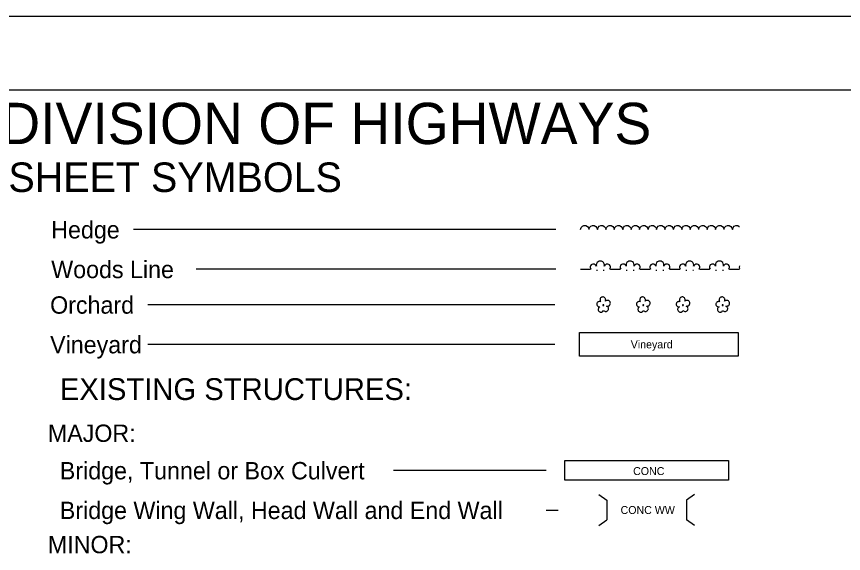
# Model space of a CAD drawing. Extents: x 0 to 3, y 0 to 1.83.
# Drawn here: x 1.443 to 2.143, y 1.378 to 1.833 of the extents above; entities that cross this region are included whole.
import ezdxf

# ---------------------------------------------------------------- set-up
doc = ezdxf.new("R2010")
doc.units = 0
for name, color, linetype in [('Sheet_Plan', 7, 'Continuous'), ('Sheet_Symbology', 7, 'Continuous'), ('z - Construction', 7, 'Continuous')]:
    doc.layers.add(name, color=color, linetype=linetype)

msp = doc.modelspace()

# ---------------------------------------------------------------- linework, layer by layer
at = {"layer": 'Sheet_Plan'}
msp.add_line((2.77083, 1.77083), (0.06249, 1.77083), dxfattribs=at)
at = {"layer": 'Sheet_Symbology'}
for p, q in [((1.89995, 1.6528), (1.54231, 1.6528)), ((1.92079, 1.6528), (1.9213, 1.6544)), ((1.9213, 1.6544), (1.92231, 1.65549)), ((1.92231, 1.65549), (1.92365, 1.65625)), ((1.92365, 1.65625), (1.92525, 1.65625)), ((1.92525, 1.65625), (1.92659, 1.65541)), ((1.92659, 1.65541), (1.92752, 1.65431)), ((1.92752, 1.65431), (1.92786, 1.65288)), ((1.92794, 1.6528), (1.92844, 1.6544)), ((1.92844, 1.6544), (1.92945, 1.65549)), ((1.92945, 1.65549), (1.9308, 1.65625)), ((1.9308, 1.65625), (1.9324, 1.65625)), ((1.9324, 1.65625), (1.93374, 1.65541)), ((1.93374, 1.65541), (1.93467, 1.65431)), ((1.93467, 1.65431), (1.935, 1.65288)), ((1.93509, 1.6528), (1.93559, 1.6544)), ((1.93559, 1.6544), (1.9366, 1.65549)), ((1.9366, 1.65549), (1.93795, 1.65625)), ((1.93795, 1.65625), (1.93954, 1.65625)), ((1.93954, 1.65625), (1.94089, 1.65541)), ((1.94089, 1.65541), (1.94181, 1.65431)), ((1.94181, 1.65431), (1.94215, 1.65288)), ((1.94223, 1.6528), (1.94274, 1.6544)), ((1.94274, 1.6544), (1.94375, 1.65549)), ((1.94375, 1.65549), (1.94509, 1.65625)), ((1.94509, 1.65625), (1.94669, 1.65625)), ((1.94669, 1.65625), (1.94803, 1.65541)), ((1.94803, 1.65541), (1.94896, 1.65431)), ((1.94896, 1.65431), (1.9493, 1.65288)), ((1.94938, 1.6528), (1.94988, 1.6544)), ((1.94988, 1.6544), (1.95089, 1.65549)), ((1.95089, 1.65549), (1.95224, 1.65625)), ((1.95224, 1.65625), (1.95384, 1.65625)), ((1.95384, 1.65625), (1.95518, 1.65541)), ((1.95518, 1.65541), (1.95611, 1.65431)), ((1.95611, 1.65431), (1.95644, 1.65288)), ((1.95653, 1.6528), (1.95703, 1.6544)), ((1.95703, 1.6544), (1.95804, 1.65549)), ((1.95804, 1.65549), (1.95939, 1.65625)), ((1.95939, 1.65625), (1.96098, 1.65625)), ((1.96098, 1.65625), (1.96233, 1.65541)), ((1.96233, 1.65541), (1.96325, 1.65431)), ((1.96325, 1.65431), (1.96359, 1.65288)), ((1.96367, 1.6528), (1.96418, 1.6544)), ((1.96418, 1.6544), (1.96519, 1.65549)), ((1.96519, 1.65549), (1.96653, 1.65625)), ((1.96653, 1.65625), (1.96813, 1.65625)), ((1.96813, 1.65625), (1.96947, 1.65541)), ((1.96947, 1.65541), (1.9704, 1.65431)), ((1.9704, 1.65431), (1.97074, 1.65288)), ((1.97082, 1.6528), (1.97132, 1.6544)), ((1.97132, 1.6544), (1.97233, 1.65549)), ((1.97233, 1.65549), (1.97368, 1.65625)), ((1.97368, 1.65625), (1.97528, 1.65625)), ((1.97528, 1.65625), (1.97662, 1.65541)), ((1.97662, 1.65541), (1.97755, 1.65431)), ((1.97755, 1.65431), (1.97788, 1.65288)), ((1.97797, 1.6528), (1.97847, 1.6544)), ((1.97847, 1.6544), (1.97948, 1.65549)), ((1.97948, 1.65549), (1.98083, 1.65625)), ((1.98083, 1.65625), (1.98242, 1.65625)), ((1.98242, 1.65625), (1.98377, 1.65541)), ((1.98377, 1.65541), (1.98469, 1.65431)), ((1.98469, 1.65431), (1.98503, 1.65288)), ((1.98511, 1.6528), (1.98562, 1.6544)), ((1.98562, 1.6544), (1.98663, 1.65549)), ((1.98663, 1.65549), (1.98797, 1.65625)), ((1.98797, 1.65625), (1.98957, 1.65625)), ((1.98957, 1.65625), (1.99091, 1.65541)), ((1.99091, 1.65541), (1.99184, 1.65431)), ((1.99184, 1.65431), (1.99218, 1.65288)), ((1.99226, 1.6528), (1.99276, 1.6544)), ((1.99276, 1.6544), (1.99377, 1.65549)), ((1.99377, 1.65549), (1.99512, 1.65625)), ((1.99512, 1.65625), (1.99672, 1.65625)), ((1.99672, 1.65625), (1.99806, 1.65541)), ((1.99806, 1.65541), (1.99899, 1.65431)), ((1.99899, 1.65431), (1.99932, 1.65288)), ((1.99941, 1.6528), (1.99991, 1.6544)), ((1.99991, 1.6544), (2.00092, 1.65549)), ((2.00092, 1.65549), (2.00227, 1.65625)), ((2.00227, 1.65625), (2.00386, 1.65625)), ((2.00386, 1.65625), (2.00521, 1.65541)), ((2.00521, 1.65541), (2.00613, 1.65431)), ((2.00613, 1.65431), (2.00647, 1.65288)), ((2.00655, 1.6528), (2.00706, 1.6544)), ((2.00706, 1.6544), (2.00807, 1.65549)), ((2.00807, 1.65549), (2.00941, 1.65625)), ((2.00941, 1.65625), (2.01101, 1.65625)), ((2.01101, 1.65625), (2.01235, 1.65541)), ((2.01235, 1.65541), (2.01328, 1.65431)), ((2.01328, 1.65431), (2.01362, 1.65288)), ((2.0137, 1.6528), (2.0142, 1.6544)), ((2.0142, 1.6544), (2.01521, 1.65549)), ((2.01521, 1.65549), (2.01656, 1.65625)), ((2.01656, 1.65625), (2.01816, 1.65625)), ((2.01816, 1.65625), (2.0195, 1.65541)), ((2.0195, 1.65541), (2.02043, 1.65431)), ((2.02043, 1.65431), (2.02076, 1.65288)), ((2.02085, 1.6528), (2.02135, 1.6544)), ((2.02135, 1.6544), (2.02236, 1.65549)), ((2.02236, 1.65549), (2.02371, 1.65625)), ((2.02371, 1.65625), (2.0253, 1.65625)), ((2.0253, 1.65625), (2.02665, 1.65541)), ((2.02665, 1.65541), (2.02757, 1.65431)), ((2.02757, 1.65431), (2.02791, 1.65288)), ((2.02799, 1.6528), (2.0285, 1.6544)), ((2.0285, 1.6544), (2.02951, 1.65549)), ((2.02951, 1.65549), (2.03085, 1.65625)), ((2.03085, 1.65625), (2.03245, 1.65625)), ((2.03245, 1.65625), (2.03379, 1.65541)), ((2.03379, 1.65541), (2.03472, 1.65431)), ((2.03472, 1.65431), (2.03506, 1.65288)), ((2.03514, 1.6528), (2.03564, 1.6544)), ((2.03564, 1.6544), (2.03665, 1.65549)), ((2.03665, 1.65549), (2.038, 1.65625)), ((2.038, 1.65625), (2.0396, 1.65625)), ((2.0396, 1.65625), (2.04094, 1.65541)), ((2.04094, 1.65541), (2.04187, 1.65431)), ((2.04187, 1.65431), (2.0422, 1.65288)), ((2.04229, 1.6528), (2.04279, 1.6544)), ((2.04279, 1.6544), (2.0438, 1.65549)), ((2.0438, 1.65549), (2.04515, 1.65625)), ((2.04515, 1.65625), (2.04674, 1.65625)), ((2.04674, 1.65625), (2.04809, 1.65541)), ((2.04809, 1.65541), (2.04901, 1.65431)), ((2.04901, 1.65431), (2.04935, 1.65288)), ((2.04943, 1.6528), (2.04994, 1.6544)), ((2.04994, 1.6544), (2.05095, 1.65549)), ((2.05095, 1.65549), (2.05229, 1.65625)), ((2.05229, 1.65625), (2.05389, 1.65625)), ((2.05389, 1.65625), (2.05523, 1.65541)), ((2.05523, 1.65541), (2.05532, 1.65532)), ((1.89995, 1.61917), (1.59538, 1.61917)), ((1.92079, 1.61917), (1.9292, 1.61917)), ((1.93416, 1.61833), (1.935, 1.61833)), ((1.94005, 1.61833), (1.94089, 1.61833)), ((1.94602, 1.61917), (1.95442, 1.61917)), ((1.95939, 1.61833), (1.96023, 1.61833)), ((1.96527, 1.61833), (1.96611, 1.61833)), ((1.97124, 1.61917), (1.97965, 1.61917)), ((1.98461, 1.61833), (1.98545, 1.61833)), ((1.99049, 1.61833), (1.99134, 1.61833)), ((1.99646, 1.61917), (2.00487, 1.61917)), ((2.00983, 1.61833), (2.01067, 1.61833)), ((2.01572, 1.61833), (2.01656, 1.61833)), ((2.02169, 1.61917), (2.0301, 1.61917)), ((2.03506, 1.61833), (2.0359, 1.61833)), ((2.04094, 1.61833), (2.04178, 1.61833)), ((2.04691, 1.61917), (2.05532, 1.61917)), ((1.899, 1.58902), (1.55439, 1.58902)), ((1.899, 1.55539), (1.55439, 1.55539)), ((1.89175, 1.4486), (1.76232, 1.4486)), ((1.93622, 1.42819), (1.94312, 1.42338)), ((1.94312, 1.42338), (1.94312, 1.40656)), ((2.01728, 1.42819), (2.01038, 1.42338)), ((2.01038, 1.42338), (2.01038, 1.40656)), ((1.89175, 1.41497), (1.90182, 1.41497)), ((1.93622, 1.40175), (1.94312, 1.40656)), ((2.01728, 1.40175), (2.01038, 1.40656))]:
    msp.add_line(p, q, dxfattribs=at)
for points in [[(1.94179, 1.59196), (1.94204, 1.59247), (1.94212, 1.59297), (1.94204, 1.59348), (1.94196, 1.59398), (1.9417, 1.5944), (1.94145, 1.59482), (1.94103, 1.59516), (1.94061, 1.59541), (1.94002, 1.59558), (1.9396, 1.59558), (1.9391, 1.5955), (1.93859, 1.59533), (1.93817, 1.59508), (1.93775, 1.59474), (1.9375, 1.59423), (1.93733, 1.59381), (1.93725, 1.59331), (1.93725, 1.59281), (1.93733, 1.5923), (1.93758, 1.59188), (1.93792, 1.59138), (1.9375, 1.59163), (1.93699, 1.59171), (1.93649, 1.59171), (1.93607, 1.59154), (1.93565, 1.59138), (1.93523, 1.59104), (1.93489, 1.5907), (1.93464, 1.59028), (1.93456, 1.58986), (1.93447, 1.58927), (1.93456, 1.58885), (1.93472, 1.58843), (1.93506, 1.58801), (1.93531, 1.58768), (1.93573, 1.58742), (1.93624, 1.58717), (1.93666, 1.58709), (1.93716, 1.58709), (1.93674, 1.58692), (1.93632, 1.58658), (1.93607, 1.58625), (1.9359, 1.58574), (1.93573, 1.58524), (1.93573, 1.58482), (1.93582, 1.58431), (1.93607, 1.58389), (1.93632, 1.58347), (1.93666, 1.58314), (1.93708, 1.58288), (1.9375, 1.58272), (1.938, 1.58272), (1.93851, 1.58272), (1.93893, 1.5828), (1.93935, 1.58314), (1.93977, 1.58339), (1.94019, 1.58415)], [(1.94019, 1.58415), (1.9412, 1.58356), (1.9417, 1.58339), (1.94221, 1.5833), (1.94271, 1.58339), (1.94313, 1.58356), (1.94355, 1.58381), (1.94397, 1.58415), (1.94423, 1.58457), (1.94439, 1.58499), (1.94456, 1.58549), (1.94448, 1.586), (1.94439, 1.5865), (1.94406, 1.587), (1.94381, 1.58734), (1.94338, 1.58759), (1.94288, 1.58785), (1.94338, 1.58776), (1.94397, 1.58776), (1.94439, 1.58793), (1.9449, 1.58818), (1.94532, 1.58843), (1.94565, 1.58885), (1.94591, 1.58936), (1.94599, 1.58986), (1.94608, 1.59037), (1.94599, 1.59087), (1.94582, 1.59138), (1.94549, 1.5918), (1.94507, 1.59222), (1.94465, 1.59247), (1.94414, 1.59264), (1.94364, 1.59272), (1.94313, 1.59272), (1.94263, 1.59255), (1.94221, 1.5923), (1.94179, 1.59196)], [(1.97542, 1.59196), (1.97567, 1.59247), (1.97575, 1.59297), (1.97567, 1.59348), (1.97559, 1.59398), (1.97533, 1.5944), (1.97508, 1.59482), (1.97466, 1.59516), (1.97424, 1.59541), (1.97365, 1.59558), (1.97323, 1.59558), (1.97273, 1.5955), (1.97222, 1.59533), (1.9718, 1.59508), (1.97138, 1.59474), (1.97113, 1.59423), (1.97096, 1.59381), (1.97088, 1.59331), (1.97088, 1.59281), (1.97096, 1.5923), (1.97121, 1.59188), (1.97155, 1.59138), (1.97113, 1.59163), (1.97063, 1.59171), (1.97012, 1.59171), (1.9697, 1.59154), (1.96928, 1.59138), (1.96886, 1.59104), (1.96852, 1.5907), (1.96827, 1.59028), (1.96819, 1.58986), (1.9681, 1.58927), (1.96819, 1.58885), (1.96836, 1.58843), (1.96869, 1.58801), (1.96894, 1.58768), (1.96937, 1.58742), (1.96987, 1.58717), (1.97029, 1.58709), (1.97079, 1.58709), (1.97037, 1.58692), (1.96995, 1.58658), (1.9697, 1.58625), (1.96953, 1.58574), (1.96937, 1.58524), (1.96937, 1.58482), (1.96945, 1.58431), (1.9697, 1.58389), (1.96995, 1.58347), (1.97029, 1.58314), (1.97071, 1.58288), (1.97113, 1.58272), (1.97164, 1.58272), (1.97214, 1.58272), (1.97256, 1.5828), (1.97298, 1.58314), (1.9734, 1.58339), (1.97382, 1.58415)], [(1.97382, 1.58415), (1.97483, 1.58356), (1.97533, 1.58339), (1.97584, 1.5833), (1.97634, 1.58339), (1.97676, 1.58356), (1.97718, 1.58381), (1.9776, 1.58415), (1.97786, 1.58457), (1.97803, 1.58499), (1.97819, 1.58549), (1.97811, 1.586), (1.97803, 1.5865), (1.97769, 1.587), (1.97744, 1.58734), (1.97702, 1.58759), (1.97651, 1.58785), (1.97702, 1.58776), (1.9776, 1.58776), (1.97803, 1.58793), (1.97853, 1.58818), (1.97895, 1.58843), (1.97929, 1.58885), (1.97954, 1.58936), (1.97962, 1.58986), (1.97971, 1.59037), (1.97962, 1.59087), (1.97945, 1.59138), (1.97912, 1.5918), (1.9787, 1.59222), (1.97828, 1.59247), (1.97777, 1.59264), (1.97727, 1.59272), (1.97676, 1.59272), (1.97626, 1.59255), (1.97584, 1.5923), (1.97542, 1.59196)], [(2.00905, 1.59196), (2.0093, 1.59247), (2.00939, 1.59297), (2.0093, 1.59348), (2.00922, 1.59398), (2.00897, 1.5944), (2.00871, 1.59482), (2.00829, 1.59516), (2.00787, 1.59541), (2.00728, 1.59558), (2.00686, 1.59558), (2.00636, 1.5955), (2.00585, 1.59533), (2.00543, 1.59508), (2.00501, 1.59474), (2.00476, 1.59423), (2.00459, 1.59381), (2.00451, 1.59331), (2.00451, 1.59281), (2.00459, 1.5923), (2.00485, 1.59188), (2.00518, 1.59138), (2.00476, 1.59163), (2.00426, 1.59171), (2.00375, 1.59171), (2.00333, 1.59154), (2.00291, 1.59138), (2.00249, 1.59104), (2.00216, 1.5907), (2.0019, 1.59028), (2.00182, 1.58986), (2.00174, 1.58927), (2.00182, 1.58885), (2.00199, 1.58843), (2.00232, 1.58801), (2.00258, 1.58768), (2.003, 1.58742), (2.0035, 1.58717), (2.00392, 1.58709), (2.00443, 1.58709), (2.00401, 1.58692), (2.00358, 1.58658), (2.00333, 1.58625), (2.00316, 1.58574), (2.003, 1.58524), (2.003, 1.58482), (2.00308, 1.58431), (2.00333, 1.58389), (2.00358, 1.58347), (2.00392, 1.58314), (2.00434, 1.58288), (2.00476, 1.58272), (2.00527, 1.58272), (2.00577, 1.58272), (2.00619, 1.5828), (2.00661, 1.58314), (2.00703, 1.58339), (2.00745, 1.58415)], [(2.00745, 1.58415), (2.00846, 1.58356), (2.00897, 1.58339), (2.00947, 1.5833), (2.00997, 1.58339), (2.0104, 1.58356), (2.01082, 1.58381), (2.01124, 1.58415), (2.01149, 1.58457), (2.01166, 1.58499), (2.01182, 1.58549), (2.01174, 1.586), (2.01166, 1.5865), (2.01132, 1.587), (2.01107, 1.58734), (2.01065, 1.58759), (2.01014, 1.58785), (2.01065, 1.58776), (2.01124, 1.58776), (2.01166, 1.58793), (2.01216, 1.58818), (2.01258, 1.58843), (2.01292, 1.58885), (2.01317, 1.58936), (2.01325, 1.58986), (2.01334, 1.59037), (2.01325, 1.59087), (2.01309, 1.59138), (2.01275, 1.5918), (2.01233, 1.59222), (2.01191, 1.59247), (2.0114, 1.59264), (2.0109, 1.59272), (2.0104, 1.59272), (2.00989, 1.59255), (2.00947, 1.5923), (2.00905, 1.59196)], [(2.04268, 1.59196), (2.04293, 1.59247), (2.04302, 1.59297), (2.04293, 1.59348), (2.04285, 1.59398), (2.0426, 1.5944), (2.04234, 1.59482), (2.04192, 1.59516), (2.0415, 1.59541), (2.04092, 1.59558), (2.0405, 1.59558), (2.03999, 1.5955), (2.03949, 1.59533), (2.03907, 1.59508), (2.03865, 1.59474), (2.03839, 1.59423), (2.03823, 1.59381), (2.03814, 1.59331), (2.03814, 1.59281), (2.03823, 1.5923), (2.03848, 1.59188), (2.03881, 1.59138), (2.03839, 1.59163), (2.03789, 1.59171), (2.03738, 1.59171), (2.03696, 1.59154), (2.03654, 1.59138), (2.03612, 1.59104), (2.03579, 1.5907), (2.03553, 1.59028), (2.03545, 1.58986), (2.03537, 1.58927), (2.03545, 1.58885), (2.03562, 1.58843), (2.03595, 1.58801), (2.03621, 1.58768), (2.03663, 1.58742), (2.03713, 1.58717), (2.03755, 1.58709), (2.03806, 1.58709), (2.03764, 1.58692), (2.03722, 1.58658), (2.03696, 1.58625), (2.0368, 1.58574), (2.03663, 1.58524), (2.03663, 1.58482), (2.03671, 1.58431), (2.03696, 1.58389), (2.03722, 1.58347), (2.03755, 1.58314), (2.03797, 1.58288), (2.03839, 1.58272), (2.0389, 1.58272), (2.0394, 1.58272), (2.03982, 1.5828), (2.04024, 1.58314), (2.04066, 1.58339), (2.04108, 1.58415)], [(2.04108, 1.58415), (2.04209, 1.58356), (2.0426, 1.58339), (2.0431, 1.5833), (2.04361, 1.58339), (2.04403, 1.58356), (2.04445, 1.58381), (2.04487, 1.58415), (2.04512, 1.58457), (2.04529, 1.58499), (2.04546, 1.58549), (2.04537, 1.586), (2.04529, 1.5865), (2.04495, 1.587), (2.0447, 1.58734), (2.04428, 1.58759), (2.04377, 1.58785), (2.04428, 1.58776), (2.04487, 1.58776), (2.04529, 1.58793), (2.04579, 1.58818), (2.04621, 1.58843), (2.04655, 1.58885), (2.0468, 1.58936), (2.04689, 1.58986), (2.04697, 1.59037), (2.04689, 1.59087), (2.04672, 1.59138), (2.04638, 1.5918), (2.04596, 1.59222), (2.04554, 1.59247), (2.04504, 1.59264), (2.04453, 1.59272), (2.04403, 1.59272), (2.04352, 1.59255), (2.0431, 1.5923), (2.04268, 1.59196)], [(1.94036, 1.58902), (1.94011, 1.58902), (1.93994, 1.58894), (1.93977, 1.58885), (1.93977, 1.5886), (1.93977, 1.58843), (1.93994, 1.58827), (1.94019, 1.58827), (1.94036, 1.58827), (1.94053, 1.58843), (1.94061, 1.58869), (1.94053, 1.58885), (1.94036, 1.58902)], [(1.97399, 1.58902), (1.97374, 1.58902), (1.97357, 1.58894), (1.9734, 1.58885), (1.9734, 1.5886), (1.9734, 1.58843), (1.97357, 1.58827), (1.97382, 1.58827), (1.97399, 1.58827), (1.97416, 1.58843), (1.97424, 1.58869), (1.97416, 1.58885), (1.97399, 1.58902)], [(2.00762, 1.58902), (2.00737, 1.58902), (2.0072, 1.58894), (2.00703, 1.58885), (2.00703, 1.5886), (2.00703, 1.58843), (2.0072, 1.58827), (2.00745, 1.58827), (2.00762, 1.58827), (2.00779, 1.58843), (2.00787, 1.58869), (2.00779, 1.58885), (2.00762, 1.58902)], [(2.04125, 1.58902), (2.041, 1.58902), (2.04083, 1.58894), (2.04066, 1.58885), (2.04066, 1.5886), (2.04066, 1.58843), (2.04083, 1.58827), (2.04108, 1.58827), (2.04125, 1.58827), (2.04142, 1.58843), (2.0415, 1.58869), (2.04142, 1.58885), (2.04125, 1.58902)], [(1.91984, 1.56548), (2.05437, 1.56548), (2.05437, 1.5453), (1.91984, 1.5453), (1.91984, 1.56548)], [(1.90739, 1.45701), (2.04611, 1.45701), (2.04611, 1.44019), (1.90739, 1.44019), (1.90739, 1.45701)]]:
    msp.add_lwpolyline(points, dxfattribs=at)
for centre, radius, start, end in [((1.93753, 1.62256), 0.00347, 345.96376, 194.03624), ((1.96274, 1.62256), 0.00347, 345.96376, 194.03624), ((1.98797, 1.62256), 0.00347, 345.96376, 194.03624), ((2.01319, 1.62256), 0.00347, 345.96376, 194.03624), ((2.03841, 1.62256), 0.00347, 345.96376, 194.03624), ((1.93164, 1.62087), 0.00266, 18.43495, 219.23152), ((1.94341, 1.62087), 0.00266, 320.76848, 161.56505), ((1.95686, 1.62087), 0.00266, 18.43495, 219.23152), ((1.96863, 1.62087), 0.00266, 320.76848, 161.56505), ((1.98208, 1.62087), 0.00266, 18.43495, 219.23152), ((1.99385, 1.62087), 0.00266, 320.76848, 161.56505), ((2.00731, 1.62087), 0.00266, 18.43495, 219.23152), ((2.01908, 1.62087), 0.00266, 320.76848, 161.56505), ((2.03253, 1.62087), 0.00266, 18.43495, 219.23152), ((2.0443, 1.62087), 0.00266, 320.76848, 161.56505), ((2.05775, 1.62087), 0.00266, 156.25102, 203.74899)]:
    msp.add_arc(centre, radius, start, end, dxfattribs=at)
at = {"layer": 'z - Construction'}
msp.add_line((2.83333, 1.83333), (0, 1.83333), dxfattribs=at)

# ---------------------------------------------------------------- texts
at = {"layer": 'Sheet_Symbology'}
for s, height, p in [('STATE OF NORTH CAROLINA, DIVISION OF HIGHWAYS', 0.035, (0.7429, 1.72519)), ('CONVENTIONAL  PLAN SHEET SYMBOLS', 0.025, (1.05732, 1.68458)), ('Hedge', 0.014714, (1.47256, 1.64519)), ('Woods Line', 0.014714, (1.47256, 1.61156)), ('Orchard', 0.014714, (1.47161, 1.58141)), ('Vineyard', 0.014714, (1.47161, 1.54778)), ('EXISTING STRUCTURES:', 0.0184972, (1.47983, 1.50821)), ('MAJOR:', 0.014714, (1.4697, 1.47271)), ('Bridge, Tunnel or Box Culvert', 0.0147137, (1.47983, 1.44095)), ('CONC', 0.006726, (1.96529, 1.44463)), ('Bridge Wing Wall, Head Wall and End Wall', 0.0147137, (1.47983, 1.40732)), ('MINOR:', 0.014714, (1.4697, 1.37833))]:
    msp.add_text(s, height=height, dxfattribs=at).set_placement(p)
for s, p in [('Vineyard', (1.96327, 1.55203)), ('CONC WW', (1.95468, 1.41161))]:
    msp.add_text(s, height=0.006726, rotation=0.00002, dxfattribs=at).set_placement(p)

doc.saveas('drawing.dxf')
